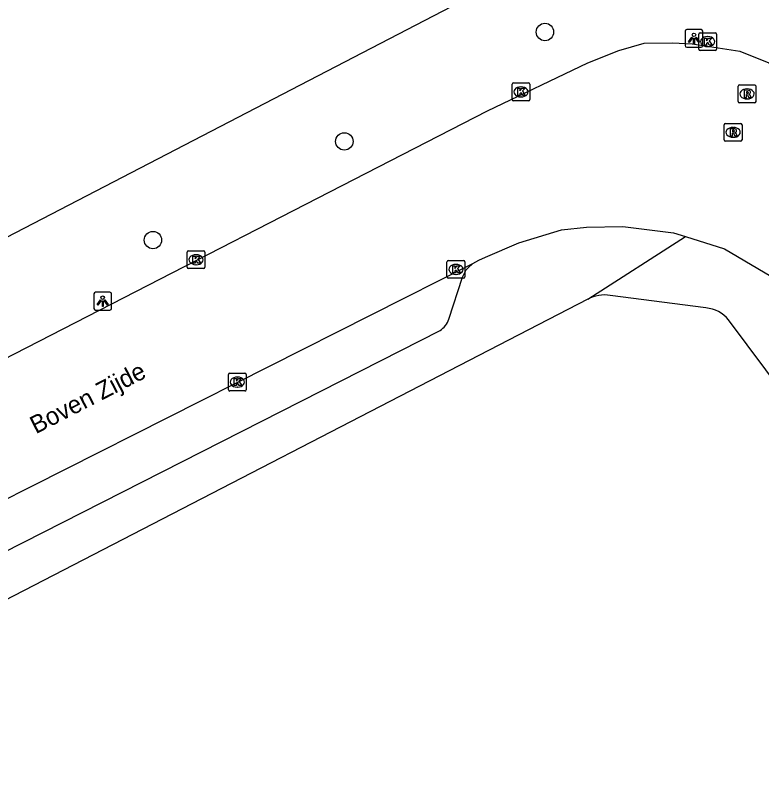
# Model space of a CAD drawing. Extents: x 156651 to 158072, y 387631 to 388990.
# Drawn here: x 157629.49 to 157671.4, y 388622.71 to 388665.96 of the extents above; entities that cross this region are included whole.
import ezdxf

# ---------------------------------------------------------------- set-up
doc = ezdxf.new("R2010")
doc.units = 0
for name, color, linetype in [('IMGEO_Boom', 7, 'Continuous'), ('IMGEO_Groenvoorziening', 7, 'Continuous'), ('IMGEO_Kolk', 7, 'Continuous'), ('IMGEO_Lichtpunt', 7, 'Continuous'), ('IMGEO_Openbare_ruimte_label', 7, 'Continuous'), ('IMGEO_Rijbaan_lokaal_gesloten', 7, 'Continuous'), ('IMGEO_Rioolput', 7, 'Continuous'), ('IMGEO_Voetpad_open', 7, 'Continuous')]:
    doc.layers.add(name, color=color, linetype=linetype)

msp = doc.modelspace()

# ---------------------------------------------------------------- linework, layer by layer
at = {"layer": 'IMGEO_Boom'}
for centre in [(157659.229, 388665.026), (157647.96, 388658.881), (157637.212, 388653.342)]:
    msp.add_circle(centre, 0.489, dxfattribs=at)
at = {"layer": 'IMGEO_Groenvoorziening'}
msp.add_lwpolyline([(157673.726, 388668.041), (157670.98, 388669.045), (157663.857, 388670.063), (157657.977, 388668.537), (157609.481, 388643.37), (157537.398, 388603.555)], dxfattribs=at)
at = {"layer": 'IMGEO_Kolk'}
for p, q in [((157667.866, 388664.062), (157667.866, 388664.914)), ((157667.941, 388664.988), (157668.793, 388664.988)), ((157668.867, 388664.914), (157668.867, 388664.062)), ((157668.354, 388664.768), (157668.379, 388664.768)), ((157668.793, 388663.988), (157667.941, 388663.988)), ((157668.377, 388664.208), (157668.352, 388664.208)), ((157657.38, 388661.239), (157657.38, 388662.091)), ((157657.455, 388662.165), (157658.307, 388662.165)), ((157657.868, 388661.945), (157657.893, 388661.945)), ((157658.381, 388662.091), (157658.381, 388661.239)), ((157657.891, 388661.385), (157657.866, 388661.385)), ((157658.307, 388661.165), (157657.455, 388661.165)), ((157639.207, 388652.74), (157640.059, 388652.74)), ((157639.132, 388651.814), (157639.132, 388652.666)), ((157639.62, 388652.52), (157639.645, 388652.52)), ((157640.133, 388652.666), (157640.133, 388651.814)), ((157639.643, 388651.96), (157639.618, 388651.96)), ((157653.727, 388651.27), (157653.727, 388652.122)), ((157653.802, 388652.196), (157654.654, 388652.196)), ((157654.215, 388651.976), (157654.24, 388651.976)), ((157654.728, 388652.122), (157654.728, 388651.27)), ((157640.059, 388651.74), (157639.207, 388651.74)), ((157654.238, 388651.416), (157654.213, 388651.416)), ((157654.654, 388651.196), (157653.802, 388651.196)), ((157641.452, 388644.941), (157641.452, 388645.793)), ((157641.527, 388645.867), (157642.379, 388645.867)), ((157642.453, 388645.793), (157642.453, 388644.941)), ((157641.94, 388645.647), (157641.965, 388645.647)), ((157641.963, 388645.087), (157641.938, 388645.087)), ((157642.379, 388644.867), (157641.527, 388644.867))]:
    msp.add_line(p, q, dxfattribs=at)
for points in [[(157667.866, 388664.062), (157667.866, 388664.914)], [(157667.941, 388664.988), (157668.793, 388664.988)], [(157668.867, 388664.914), (157668.867, 388664.062)], [(157668.187, 388664.688), (157668.31, 388664.688), (157668.31, 388664.537), (157668.44, 388664.688), (157668.604, 388664.688), (157668.458, 388664.537), (157668.611, 388664.288), (157668.459, 388664.288), (157668.374, 388664.452), (157668.31, 388664.385), (157668.31, 388664.288), (157668.187, 388664.288), (157668.187, 388664.688)], [(157668.793, 388663.988), (157667.941, 388663.988)], [(157657.38, 388661.239), (157657.38, 388662.091)], [(157657.455, 388662.165), (157658.307, 388662.165)], [(157657.701, 388661.865), (157657.824, 388661.865), (157657.824, 388661.714), (157657.954, 388661.865), (157658.118, 388661.865), (157657.972, 388661.714), (157658.125, 388661.465), (157657.973, 388661.465), (157657.888, 388661.629), (157657.824, 388661.562), (157657.824, 388661.465), (157657.701, 388661.465), (157657.701, 388661.865)], [(157658.381, 388662.091), (157658.381, 388661.239)], [(157658.307, 388661.165), (157657.455, 388661.165)], [(157639.207, 388652.74), (157640.059, 388652.74)], [(157639.132, 388651.814), (157639.132, 388652.666)], [(157639.453, 388652.44), (157639.576, 388652.44), (157639.576, 388652.289), (157639.706, 388652.44), (157639.87, 388652.44), (157639.724, 388652.289), (157639.877, 388652.04), (157639.725, 388652.04), (157639.64, 388652.204), (157639.576, 388652.137), (157639.576, 388652.04), (157639.453, 388652.04), (157639.453, 388652.44)], [(157640.133, 388652.666), (157640.133, 388651.814)], [(157653.727, 388651.27), (157653.727, 388652.122)], [(157653.802, 388652.196), (157654.654, 388652.196)], [(157654.048, 388651.896), (157654.171, 388651.896), (157654.171, 388651.745), (157654.301, 388651.896), (157654.465, 388651.896), (157654.319, 388651.745), (157654.472, 388651.496), (157654.32, 388651.496), (157654.235, 388651.66), (157654.171, 388651.593), (157654.171, 388651.496), (157654.048, 388651.496), (157654.048, 388651.896)], [(157654.728, 388652.122), (157654.728, 388651.27)], [(157640.059, 388651.74), (157639.207, 388651.74)], [(157654.654, 388651.196), (157653.802, 388651.196)], [(157641.452, 388644.941), (157641.452, 388645.793)], [(157641.527, 388645.867), (157642.379, 388645.867)], [(157642.453, 388645.793), (157642.453, 388644.941)], [(157641.773, 388645.567), (157641.896, 388645.567), (157641.896, 388645.416), (157642.026, 388645.567), (157642.19, 388645.567), (157642.044, 388645.416), (157642.197, 388645.167), (157642.045, 388645.167), (157641.96, 388645.331), (157641.896, 388645.264), (157641.896, 388645.167), (157641.773, 388645.167), (157641.773, 388645.567)], [(157642.379, 388644.867), (157641.527, 388644.867)]]:
    msp.add_lwpolyline(points, dxfattribs=at)
for centre, start, end in [((157667.943, 388664.912), 91.552, 178.448), ((157667.943, 388664.912), 91.552, 178.448), ((157668.791, 388664.912), 1.552, 88.448), ((157668.791, 388664.912), 1.552, 88.448), ((157667.943, 388664.064), 181.552, 268.448), ((157667.943, 388664.064), 181.552, 268.448), ((157668.791, 388664.064), 271.552, 358.448), ((157668.791, 388664.064), 271.552, 358.448), ((157657.457, 388662.089), 91.552, 178.448), ((157657.457, 388662.089), 91.552, 178.448), ((157658.305, 388662.089), 1.552, 88.448), ((157658.305, 388662.089), 1.552, 88.448), ((157657.457, 388661.241), 181.552, 268.448), ((157657.457, 388661.241), 181.552, 268.448), ((157658.305, 388661.241), 271.552, 358.448), ((157658.305, 388661.241), 271.552, 358.448), ((157639.209, 388652.664), 91.552, 178.448), ((157639.209, 388652.664), 91.552, 178.448), ((157640.057, 388652.664), 1.552, 88.448), ((157640.057, 388652.664), 1.552, 88.448), ((157653.804, 388652.12), 91.552, 178.448), ((157653.804, 388652.12), 91.552, 178.448), ((157654.652, 388652.12), 1.552, 88.448), ((157654.652, 388652.12), 1.552, 88.448), ((157639.209, 388651.816), 181.552, 268.448), ((157639.209, 388651.816), 181.552, 268.448), ((157640.057, 388651.816), 271.552, 358.448), ((157640.057, 388651.816), 271.552, 358.448), ((157653.804, 388651.272), 181.552, 268.448), ((157653.804, 388651.272), 181.552, 268.448), ((157654.652, 388651.272), 271.552, 358.448), ((157654.652, 388651.272), 271.552, 358.448), ((157641.529, 388645.791), 91.552, 178.448), ((157641.529, 388645.791), 91.552, 178.448), ((157642.377, 388645.791), 1.552, 88.448), ((157642.377, 388645.791), 1.552, 88.448), ((157641.529, 388644.943), 181.552, 268.448), ((157641.529, 388644.943), 181.552, 268.448), ((157642.377, 388644.943), 271.552, 358.448), ((157642.377, 388644.943), 271.552, 358.448)]:
    msp.add_arc(centre, 0.0765, start, end, dxfattribs=at)
for centre, major_axis, ratio, start_param, end_param in [((157668.353, 388664.488), (-0.387, 0.002), 0.722429, 4.712389, 7.853982), ((157668.378, 388664.488), (-0.39, 0.002), 0.717154, 1.570796, 4.712389), ((157657.867, 388661.665), (-0.387, 0.002), 0.722429, 4.712389, 7.853982), ((157657.892, 388661.665), (-0.39, 0.002), 0.717154, 1.570796, 4.712389), ((157639.619, 388652.24), (-0.387, 0.002), 0.722429, 4.712389, 7.853982), ((157639.644, 388652.24), (-0.39, 0.002), 0.717154, 1.570796, 4.712389), ((157654.214, 388651.696), (-0.387, 0.002), 0.722429, 4.712389, 7.853982), ((157654.239, 388651.696), (-0.39, 0.002), 0.717154, 1.570796, 4.712389), ((157641.939, 388645.367), (-0.387, 0.002), 0.722429, 4.712389, 7.853982), ((157641.964, 388645.367), (-0.39, 0.002), 0.717154, 1.570796, 4.712389)]:
    msp.add_ellipse(centre, major_axis=major_axis, ratio=ratio, start_param=start_param, end_param=end_param, dxfattribs=at)
at = {"layer": 'IMGEO_Lichtpunt'}
for p, q in [((157667.097, 388665.07), (157667.097, 388664.263)), ((157667.097, 388665.07), (157667.097, 388664.263)), ((157667.999, 388665.165), (157667.191, 388665.165)), ((157667.999, 388665.165), (157667.191, 388665.165)), ((157668.093, 388664.263), (157668.093, 388665.07)), ((157668.093, 388664.263), (157668.093, 388665.07)), ((157667.191, 388664.169), (157667.999, 388664.169)), ((157667.191, 388664.169), (157667.999, 388664.169)), ((157633.893, 388650.314), (157633.893, 388649.507)), ((157633.893, 388650.314), (157633.893, 388649.507)), ((157634.795, 388650.409), (157633.987, 388650.409)), ((157634.795, 388650.409), (157633.987, 388650.409)), ((157634.889, 388649.507), (157634.889, 388650.314)), ((157634.889, 388649.507), (157634.889, 388650.314)), ((157633.987, 388649.413), (157634.795, 388649.413)), ((157633.987, 388649.413), (157634.795, 388649.413))]:
    msp.add_line(p, q, dxfattribs=at)
for points in [[(157667.471, 388664.734), (157667.51, 388664.706), (157667.322, 388664.444), (157667.284, 388664.471), (157667.471, 388664.734)], [(157667.573, 388664.686), (157667.62, 388664.686), (157667.62, 388664.364), (157667.573, 388664.364), (157667.573, 388664.686)], [(157667.683, 388664.706), (157667.721, 388664.733), (157667.908, 388664.471), (157667.869, 388664.443), (157667.683, 388664.706)], [(157634.267, 388649.978), (157634.306, 388649.95), (157634.118, 388649.688), (157634.08, 388649.715), (157634.267, 388649.978)], [(157634.369, 388649.93), (157634.416, 388649.93), (157634.416, 388649.608), (157634.369, 388649.608), (157634.369, 388649.93)], [(157634.479, 388649.95), (157634.517, 388649.977), (157634.704, 388649.715), (157634.665, 388649.687), (157634.479, 388649.95)]]:
    msp.add_lwpolyline(points, dxfattribs=at)
for centre in [(157667.596, 388664.868), (157634.392, 388650.112)]:
    msp.add_circle(centre, 0.0994, dxfattribs=at)
for centre, start, end in [((157667.191, 388665.07), 90, 180), ((157667.191, 388665.07), 90, 180), ((157667.999, 388665.07), 0, 90), ((157667.999, 388665.07), 0, 90), ((157667.191, 388664.263), 180, 270), ((157667.191, 388664.263), 180, 270), ((157667.999, 388664.263), 270, 0), ((157667.999, 388664.263), 270, 360), ((157633.987, 388650.314), 90, 180), ((157633.987, 388650.314), 90, 180), ((157634.795, 388650.314), 0, 90), ((157634.795, 388650.314), 0, 90), ((157633.987, 388649.507), 180, 270), ((157633.987, 388649.507), 180, 270), ((157634.795, 388649.507), 270, 0), ((157634.795, 388649.507), 270, 360)]:
    msp.add_arc(centre, 0.0946, start, end, dxfattribs=at)
at = {"layer": 'IMGEO_Rijbaan_lokaal_gesloten'}
for points in [[(157398.778, 388527.866), (157628.073, 388646.266), (157656.001, 388660.593), (157661.642, 388663.293), (157663.387, 388663.988), (157664.804, 388664.4), (157666.39, 388664.428), (157667.498, 388664.368), (157670.171, 388663.945), (157671.812, 388663.295), (157672.05, 388663.148)], [(157655.185, 388652.023), (157655.522, 388652.218), (157655.885, 388652.386), (157657.76, 388653.187), (157660.159, 388653.925), (157661.553, 388654.058), (157663.599, 388654.099), (157666.449, 388653.741), (157667.118, 388653.535)], [(157667.118, 388653.535), (157669.317, 388652.856), (157673.782, 388650.215), (157675.14, 388648.971), (157677.044, 388646.782)], [(157625.362, 388636.967), (157626.607, 388637.609), (157655.185, 388652.023)]]:
    msp.add_lwpolyline(points, dxfattribs=at)
at = {"layer": 'IMGEO_Rioolput'}
for p, q in [((157670.081, 388661.126), (157670.081, 388661.978)), ((157670.156, 388662.052), (157671.008, 388662.052)), ((157670.569, 388661.832), (157670.594, 388661.832)), ((157671.082, 388661.978), (157671.082, 388661.126)), ((157671.008, 388661.052), (157670.156, 388661.052)), ((157670.592, 388661.272), (157670.567, 388661.272)), ((157669.297, 388658.966), (157669.297, 388659.818)), ((157669.372, 388659.892), (157670.224, 388659.892)), ((157669.785, 388659.672), (157669.81, 388659.672)), ((157670.298, 388659.818), (157670.298, 388658.966)), ((157670.224, 388658.892), (157669.372, 388658.892)), ((157669.808, 388659.112), (157669.783, 388659.112))]:
    msp.add_line(p, q, dxfattribs=at)
for points in [[(157670.081, 388661.126), (157670.081, 388661.978)], [(157670.156, 388662.052), (157671.008, 388662.052)], [(157671.082, 388661.978), (157671.082, 388661.126)], [(157670.67, 388661.75), (157670.418, 388661.752), (157670.418, 388661.352)], [(157670.418, 388661.352), (157670.542, 388661.352), (157670.542, 388661.514), (157670.553, 388661.514)], [(157670.596, 388661.671), (157670.542, 388661.671), (157670.542, 388661.59)], [(157670.542, 388661.59), (157670.594, 388661.59)], [(157670.6, 388661.485), (157670.671, 388661.352), (157670.811, 388661.352), (157670.746, 388661.478)], [(157671.008, 388661.052), (157670.156, 388661.052)], [(157669.297, 388658.966), (157669.297, 388659.818)], [(157669.372, 388659.892), (157670.224, 388659.892)], [(157670.298, 388659.818), (157670.298, 388658.966)], [(157669.886, 388659.59), (157669.634, 388659.592), (157669.634, 388659.192)], [(157669.634, 388659.192), (157669.758, 388659.192), (157669.758, 388659.354), (157669.769, 388659.354)], [(157669.812, 388659.511), (157669.758, 388659.511), (157669.758, 388659.43)], [(157669.758, 388659.43), (157669.81, 388659.43)], [(157669.816, 388659.325), (157669.887, 388659.192), (157670.027, 388659.192), (157669.962, 388659.318)], [(157670.224, 388658.892), (157669.372, 388658.892)]]:
    msp.add_lwpolyline(points, dxfattribs=at)
for centre, radius, start, end in [((157670.158, 388661.976), 0.0765, 91.552, 178.448), ((157670.158, 388661.976), 0.0765, 91.552, 178.448), ((157671.006, 388661.976), 0.0765, 1.552, 88.448), ((157671.006, 388661.976), 0.0765, 1.552, 88.448), ((157670.552, 388661.461), 0.0533, 26.0293, 88.6989), ((157670.578, 388661.779), 0.19, 274.7715, 282.9687), ((157670.602, 388661.575), 0.0964, 77.0061, 93.1865), ((157670.616, 388661.632), 0.0378, 276.6634, 79.6772), ((157670.669, 388661.64), 0.109, 350.3612, 89.416), ((157670.667, 388661.64), 0.112, 277.5842, 350.9817), ((157670.651, 388661.425), 0.108, 29.5134, 73.7905), ((157670.158, 388661.128), 0.0765, 181.552, 268.448), ((157670.158, 388661.128), 0.0765, 181.552, 268.448), ((157671.006, 388661.128), 0.0765, 271.552, 358.448), ((157671.006, 388661.128), 0.0765, 271.552, 358.448), ((157669.374, 388659.816), 0.0765, 91.552, 178.448), ((157669.374, 388659.816), 0.0765, 91.552, 178.448), ((157670.222, 388659.816), 0.0765, 1.552, 88.448), ((157670.222, 388659.816), 0.0765, 1.552, 88.448), ((157669.768, 388659.301), 0.0533, 26.0293, 88.6989), ((157669.794, 388659.619), 0.19, 274.7715, 282.9687), ((157669.818, 388659.415), 0.0964, 77.0061, 93.1865), ((157669.832, 388659.472), 0.0378, 276.6634, 79.6772), ((157669.885, 388659.48), 0.109, 350.3612, 89.416), ((157669.883, 388659.48), 0.112, 277.5842, 350.9817), ((157669.867, 388659.265), 0.108, 29.5134, 73.7905), ((157669.374, 388658.968), 0.0765, 181.552, 268.448), ((157669.374, 388658.968), 0.0765, 181.552, 268.448), ((157670.222, 388658.968), 0.0765, 271.552, 358.448), ((157670.222, 388658.968), 0.0765, 271.552, 358.448)]:
    msp.add_arc(centre, radius, start, end, dxfattribs=at)
for centre, major_axis, ratio, start_param, end_param in [((157670.568, 388661.552), (-0.387, 0.002), 0.722429, 4.712389, 7.853982), ((157670.593, 388661.552), (-0.39, 0.002), 0.717154, 1.570796, 4.712389), ((157669.784, 388659.392), (-0.387, 0.002), 0.722429, 4.712389, 7.853982), ((157669.809, 388659.392), (-0.39, 0.002), 0.717154, 1.570796, 4.712389)]:
    msp.add_ellipse(centre, major_axis=major_axis, ratio=ratio, start_param=start_param, end_param=end_param, dxfattribs=at)
at = {"layer": 'IMGEO_Voetpad_open'}
for points in [[(157661.638, 388650.018), (157667.118, 388653.535)], [(157653.827, 388648.894), (157654.589, 388651.261), (157654.807, 388651.664)], [(157668.268, 388649.533), (157662.9, 388650.235)], [(157661.638, 388650.018), (157627.71, 388632.506)], [(157720.519, 388580.603), (157669.545, 388648.866)], [(157626.556, 388634.652), (157653.339, 388648.26)]]:
    msp.add_lwpolyline(points, dxfattribs=at)
for centre, radius, start, end in [((157656.604, 388650.15), 2.35, 127.1552, 139.8913), ((157662.581, 388648.31), 1.952, 80.6056, 118.9075), ((157668.071, 388647.6), 1.943, 40.6633, 84.1789), ((157652.663, 388649.285), 1.228, 303.3958, 341.4321)]:
    msp.add_arc(centre, radius, start, end, dxfattribs=at)

# ---------------------------------------------------------------- texts
at = {"layer": 'IMGEO_Openbare_ruimte_label'}
msp.add_text('Boven Zijde', height=1, rotation=27.2059, dxfattribs=at).set_placement((157630.633, 388642.431))

doc.saveas('drawing.dxf')
